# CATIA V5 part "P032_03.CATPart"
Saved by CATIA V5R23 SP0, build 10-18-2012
Part number: 05-LICP-T02-E-S03-P032_03
Bounding box of the stored display mesh (mm): x 0 to 2.205, y -14 to 14, z -13.955 to 13.955
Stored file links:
  C:\wamp\www\COURS\CONCEPTION GMP1\TITRE 02-SEMESTRE 2\03-TP7-PRESSE MECANIQUE\eleve\P032_03.CATPart
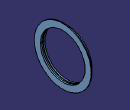
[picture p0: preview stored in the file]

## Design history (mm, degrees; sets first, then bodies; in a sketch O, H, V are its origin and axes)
Body1 (main body)
  Solid1: solid without history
